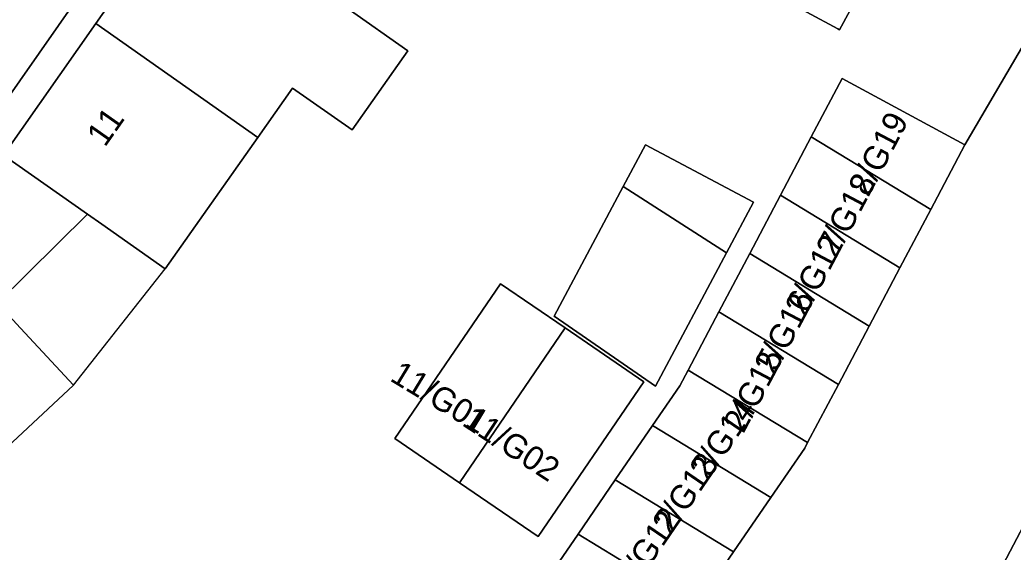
# Model space of a CAD drawing. Extents: x 161798 to 162385, y 382315 to 382833.
# Drawn here: x 161957.55 to 161998.86, y 382692.97 to 382715.1 of the extents above; entities that cross this region are included whole.
import ezdxf

# ---------------------------------------------------------------- set-up
doc = ezdxf.new("R2010")
doc.units = 0
for name, color, linetype in [('IMGEO_Erf', 7, 'Continuous'), ('IMGEO_Pand', 7, 'Continuous'), ('IMGEO_Pand_nummerreeks', 7, 'Continuous'), ('IMGEO_Pand_overbouw', 7, 'Continuous'), ('IMGEO_Rijbaan_lokaal_open', 7, 'Continuous'), ('IMGEO_Voetpad_open', 7, 'Continuous')]:
    doc.layers.add(name, color=color, linetype=linetype)

msp = doc.modelspace()

# ---------------------------------------------------------------- linework, layer by layer
at = {"layer": 'IMGEO_Erf'}
for points in [[(162000, 382748.49), (161998.309, 382750), (161995.84, 382752.203), (161995.75, 382752.284), (161993.712, 382750), (161991.488, 382747.507), (161991.557, 382747.445), (161997.283, 382742.337), (161993.653, 382738.267), (161987.136, 382742.39), (161987.064, 382742.454), (161985.478, 382743.87), (161981.747, 382747.198), (161955.826, 382710.123)], [(161979.216, 382691.456), (161980.767, 382693.716), (161982.317, 382695.976), (161983.868, 382698.237), (161984.997, 382699.882), (161985.346, 382700.542), (161986.626, 382702.966), (161987.907, 382705.391), (161989.188, 382707.815), (161990.469, 382710.24), (161991.75, 382712.664), (161996.854, 382709.902), (162005.49, 382724.651)], [(161971.206, 382715.565), (161973.691, 382713.821), (161971.373, 382710.526), (161968.888, 382712.27), (161967.445, 382710.219), (161963.599, 382704.753), (161960.963, 382706.603), (161960.358, 382707.027), (161956.87, 382709.475), (161960.71, 382714.946), (161964.465, 382720.297)], [(161956.607, 382703.318), (161957.577, 382702.279), (161959.782, 382699.919), (161954.912, 382695.382)], [(161999.451, 382694.354), (161992.884, 382681.874), (161977.339, 382656.596)]]:
    msp.add_lwpolyline(points, dxfattribs=at)
for points in [[(161989.014, 382719.297), (161990.323, 382721.718), (161994.281, 382719.576), (161992.761, 382716.766), (161991.637, 382714.69), (161991.568, 382714.727), (161991.388, 382714.824), (161987.679, 382716.831), (161987.749, 382716.961)], [(161982.651, 382708.174), (161983.579, 382709.914), (161988.066, 382707.521), (161986.941, 382705.412), (161983.989, 382699.876), (161979.776, 382702.784)], [(161973.143, 382697.692), (161977.538, 382704.131), (161980.231, 382702.293), (161983.506, 382700.057), (161979.11, 382693.617), (161975.835, 382695.853)]]:
    msp.add_lwpolyline(points, close=True, dxfattribs=at)
at = {"layer": 'IMGEO_Pand'}
for points in [[(161971.206, 382715.565), (161964.465, 382720.297), (161960.71, 382714.946), (161967.445, 382710.219), (161968.888, 382712.27), (161971.373, 382710.526), (161973.691, 382713.821)], [(161989.014, 382719.297), (161987.749, 382716.961), (161987.679, 382716.831), (161991.388, 382714.824), (161991.568, 382714.727), (161991.637, 382714.69), (161992.761, 382716.766)], [(161960.71, 382714.946), (161956.87, 382709.475), (161960.358, 382707.027), (161960.963, 382706.603), (161963.599, 382704.753), (161967.445, 382710.219)], [(161995.437, 382707.22), (161996.854, 382709.902), (161991.75, 382712.664), (161990.469, 382710.24)], [(161989.188, 382707.815), (161994.156, 382704.796), (161995.437, 382707.22), (161990.469, 382710.24)], [(161982.651, 382708.174), (161986.941, 382705.412), (161988.066, 382707.521), (161983.579, 382709.914)], [(161982.651, 382708.174), (161979.776, 382702.784), (161983.989, 382699.876), (161986.941, 382705.412)], [(161989.188, 382707.815), (161987.907, 382705.391), (161992.875, 382702.372), (161994.156, 382704.796)], [(161957.577, 382702.279), (161956.607, 382703.318), (161954.163, 382705.932), (161949.3, 382701.389), (161954.31, 382696.027), (161954.912, 382695.382), (161959.782, 382699.919)], [(161992.875, 382702.372), (161987.907, 382705.391), (161986.626, 382702.966), (161991.594, 382699.947)], [(161980.231, 382702.293), (161977.538, 382704.131), (161973.143, 382697.692), (161975.835, 382695.853)], [(161985.346, 382700.542), (161990.313, 382697.523), (161991.594, 382699.947), (161986.626, 382702.966)], [(161980.231, 382702.293), (161975.835, 382695.853), (161979.11, 382693.617), (161983.506, 382700.057)], [(161985.346, 382700.542), (161984.997, 382699.882), (161983.868, 382698.237), (161988.788, 382695.247), (161990.194, 382697.297), (161990.313, 382697.523)], [(161988.788, 382695.247), (161983.868, 382698.237), (161982.317, 382695.976), (161987.237, 382692.987)], [(161985.686, 382690.726), (161987.237, 382692.987), (161982.317, 382695.976), (161980.767, 382693.716)], [(161985.686, 382690.726), (161980.767, 382693.716), (161979.216, 382691.456), (161984.135, 382688.466)]]:
    msp.add_lwpolyline(points, close=True, dxfattribs=at)
at = {"layer": 'IMGEO_Pand_overbouw'}
for points in [[(161954.163, 382705.932), (161956.607, 382703.318), (161960.358, 382707.027), (161956.87, 382709.475)], [(161963.599, 382704.753), (161960.963, 382706.603), (161960.358, 382707.027), (161956.607, 382703.318), (161957.577, 382702.279), (161959.782, 382699.919)]]:
    msp.add_lwpolyline(points, close=True, dxfattribs=at)
at = {"layer": 'IMGEO_Rijbaan_lokaal_open'}
for points in [[(162005.49, 382724.651), (161996.854, 382709.902), (161995.437, 382707.22), (161994.156, 382704.796), (161992.875, 382702.372), (161991.594, 382699.947), (161990.313, 382697.523), (161990.194, 382697.297), (161988.788, 382695.247), (161987.237, 382692.987), (161985.686, 382690.726), (161984.135, 382688.466), (161982.584, 382686.206), (161980.341, 382682.936), (161977.97, 382680.728), (161975.868, 382678.771), (161973.767, 382676.814), (161971.665, 382674.857), (161969.563, 382672.9), (161967.462, 382670.943), (161965.36, 382668.987), (161963.289, 382667.058), (161967.593, 382662.436), (161971, 382658.776)], [(161977.339, 382656.596), (161992.884, 382681.874), (161999.451, 382694.354)]]:
    msp.add_lwpolyline(points, dxfattribs=at)
at = {"layer": 'IMGEO_Voetpad_open'}
msp.add_lwpolyline([(161953.212, 382706.879), (161955.826, 382710.123), (161981.747, 382747.198), (161984.249, 382750), (161997.519, 382764.558), (161991.848, 382768.97), (161991.783, 382769.02)], dxfattribs=at)

# ---------------------------------------------------------------- texts
at = {"layer": 'IMGEO_Pand_nummerreeks'}
for s, rotation, p in [('11', 54.9381, (161961.089, 382709.778)), ('2/G19', 62.1497, (161992.838, 382707.696)), ('2/G18', 62.1497, (161991.492, 382705.148)), ('2/G17', 62.1497, (161990.21, 382702.721)), ('2/G16', 62.1497, (161988.929, 382700.297)), ('2/G15', 62.1497, (161987.648, 382697.872)), ('11/G01', 328.8597, (161972.897, 382700.124)), ('2/G14', 55.669, (161986.158, 382695.907)), ('11/G02', 326.6137, (161975.899, 382698.271)), ('2/G13', 55.669, (161984.612, 382693.644)), ('2/G12', 55.669, (161983.063, 382691.375))]:
    msp.add_text(s, height=1, rotation=rotation, dxfattribs=at).set_placement(p)

doc.saveas('drawing.dxf')
